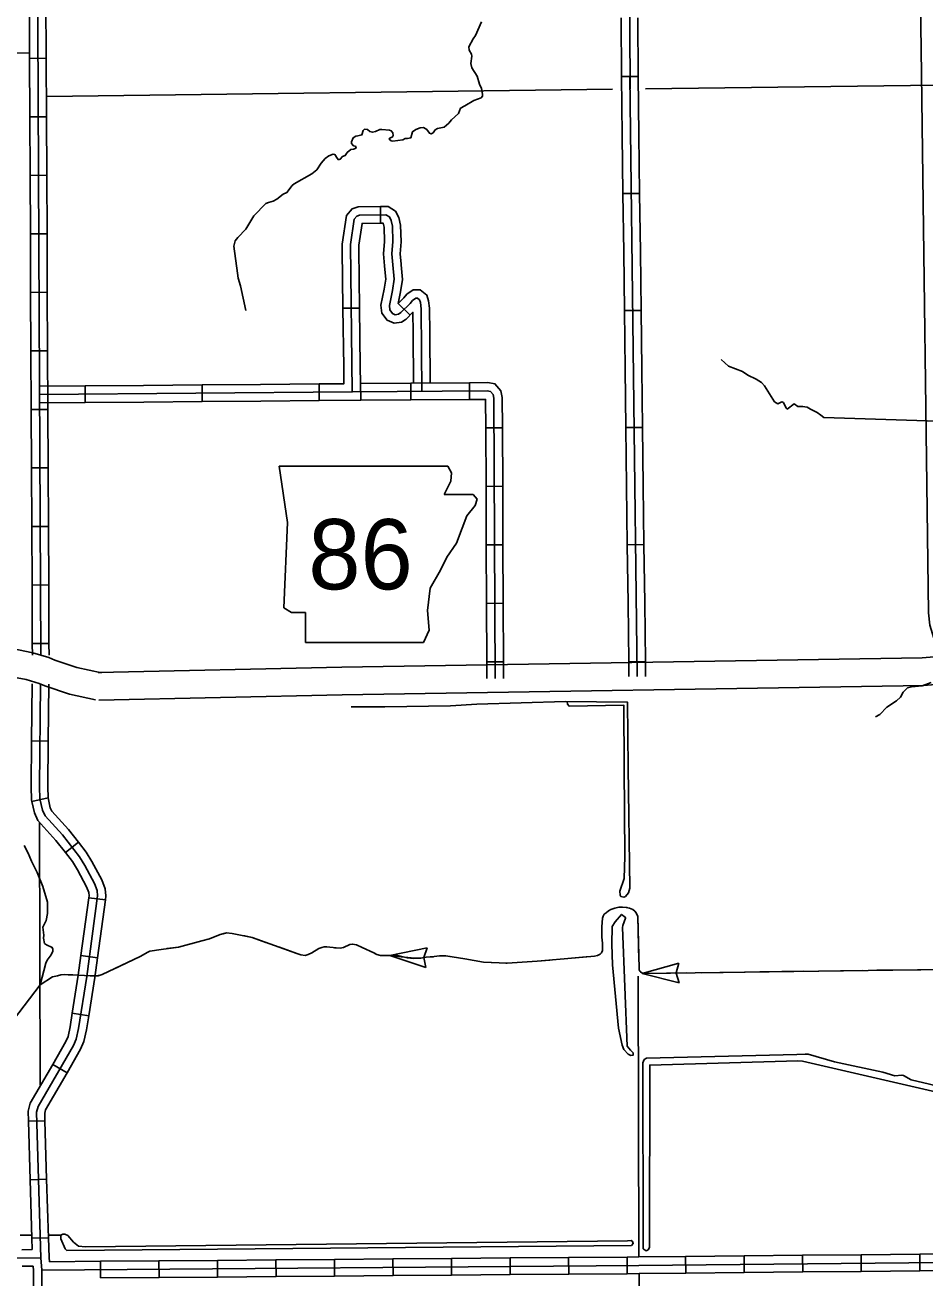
# Model space of a CAD drawing. Extents: x 982240 to 1103002, y 974866 to 1054902.
# Drawn here: x 1049490 to 1057609, y 991826 to 1003130 of the extents above; entities that cross this region are included whole.
import ezdxf

# ---------------------------------------------------------------- set-up
doc = ezdxf.new("R2010")
doc.units = 0
for name, color, linetype in [('10', 7, 'Continuous'), ('21', 7, 'Continuous'), ('32', 7, 'Continuous'), ('35', 7, 'Continuous'), ('4', 7, 'Continuous'), ('43', 7, 'Continuous'), ('45', 7, 'Continuous'), ('5', 7, 'Continuous')]:
    doc.layers.add(name, color=color, linetype=linetype)

msp = doc.modelspace()

# ---------------------------------------------------------------- linework, layer by layer
at = {"layer": '10'}
msp.add_line((1050180, 997286), (1050151, 997289), dxfattribs=at)
for points in [[(1057578, 1002688), (1057529, 1006188)], [(1059251, 997184), (1058283, 997180), (1058154, 997205), (1058053, 997239), (1057965, 997282), (1057854, 997364), (1057744, 997497), (1057688, 997597), (1057654, 997715), (1057641, 997828), (1057578, 1002688)], [(1048814, 997551), (1049247, 997522), (1049432, 997493), (1049560, 997467), (1049704, 997425), (1049760, 997400), (1049958, 997334), (1050180, 997286)], [(1050151, 997289), (1052347, 997337), (1057585, 997420), (1057692, 997430), (1057722, 997438), (1057772, 997463)], [(1050127, 997042), (1049892, 997092), (1049669, 997167), (1049617, 997190), (1049500, 997224), (1049387, 997247), (1049219, 997273), (1048798, 997302)], [(1057964, 997283), (1057942, 997268), (1057811, 997203), (1057737, 997183), (1057598, 997170), (1052351, 997087), (1050156, 997039)]]:
    msp.add_lwpolyline(points, dxfattribs=at)
at = {"layer": '21'}
for p, q in [((1051783, 999150), (1051859, 998643)), ((1053339, 999091), (1053304, 999149)), ((1053331, 999015), (1053339, 999091)), ((1053272, 998896), (1053331, 999015)), ((1053534, 998896), (1053272, 998896)), ((1053568, 998854), (1053534, 998896)), ((1053551, 998795), (1053568, 998854)), ((1053475, 998702), (1053551, 998795)), ((1051859, 998643), (1051825, 997873)), ((1053433, 998592), (1053475, 998702)), ((1053382, 998457), (1053433, 998592)), ((1053297, 998330), (1053382, 998457)), ((1053238, 998211), (1053297, 998330)), ((1053145, 998051), (1053238, 998211)), ((1053120, 997848), (1053145, 998051)), ((1051825, 997873), (1051893, 997831)), ((1051893, 997831), (1052020, 997831)), ((1052020, 997831), (1052020, 997560)), ((1053136, 997670), (1053120, 997848)), ((1053086, 997560), (1053136, 997670)), ((1052020, 997560), (1053086, 997560))]:
    msp.add_line(p, q, dxfattribs=at)
msp.add_lwpolyline([(1051783, 999150), (1053304, 999149)], dxfattribs=at)
at = {"layer": '32'}
for p, q in [((1049681, 1002831), (1049531, 1002830)), ((1049684, 1002303), (1049534, 1002302)), ((1049686, 1001775), (1049536, 1001774)), ((1049689, 1001247), (1049539, 1001246)), ((1049616, 1001142), (1049633, 997446)), ((1049691, 1000719), (1049541, 1000718)), ((1049694, 1000191), (1049544, 1000190)), ((1052972, 999749), (1052971, 999899)), ((1053500, 999752), (1053499, 999902)), ((1049696, 999663), (1049546, 999662)), ((1053647, 999496), (1053797, 999497)), ((1049699, 999135), (1049549, 999134)), ((1053650, 998968), (1053800, 998969)), ((1049701, 998607), (1049551, 998606)), ((1053652, 998440), (1053802, 998441)), ((1049704, 998079), (1049554, 998078)), ((1053654, 997912), (1053804, 997913)), ((1049706, 997551), (1049556, 997550)), ((1053657, 997384), (1053807, 997385)), ((1049699, 996670), (1049549, 996671)), ((1049699, 996158), (1049552, 996126)), ((1049972, 995757), (1049854, 995665)), ((1050215, 995237), (1050066, 995257)), ((1050144, 994714), (1049995, 994734)), ((1050065, 994190), (1049916, 994214)), ((1049870, 993678), (1049740, 993753)), ((1049670, 993244), (1049520, 993240)), ((1049685, 992716), (1049536, 992712)), ((1049701, 992189), (1049551, 992184)), ((1049554, 992082), (1049551, 992184)), ((1049462, 992081), (1049554, 992082)), ((1049710, 991972), (1050170, 991976)), ((1050171, 991826), (1050170, 991976)), ((1050699, 991830), (1050698, 991980)), ((1051227, 991834), (1051226, 991984)), ((1051755, 991839), (1051754, 991989)), ((1052283, 991843), (1052282, 991993)), ((1052811, 991847), (1052810, 991997)), ((1053339, 991851), (1053338, 992001)), ((1053867, 991856), (1053866, 992006)), ((1054395, 991860), (1054394, 992010)), ((1054923, 991864), (1054922, 992014)), ((1055451, 991869), (1055450, 992019)), ((1055979, 991875), (1055978, 992025)), ((1056507, 991880), (1056506, 992030)), ((1057035, 991885), (1057034, 992035)), ((1057563, 991891), (1057562, 992041)), ((1049464, 991931), (1049563, 991932))]:
    msp.add_line(p, q, dxfattribs=at)
for points in [[(1049540, 1018049), (1049562, 1016898), (1049558, 1016757), (1049533, 1016348), (1049537, 1015835), (1049536, 1013831), (1049577, 1008327), (1049592, 1007765), (1049585, 1007779), (1049616, 1001142)], [(1049529, 1003358), (1049531, 1002830)], [(1049679, 1003359), (1049681, 1002831)], [(1049531, 1002830), (1049534, 1002302)], [(1049681, 1002831), (1049684, 1002303)], [(1049534, 1002302), (1049536, 1001774)], [(1049684, 1002303), (1049686, 1001775)], [(1049536, 1001774), (1049539, 1001246)], [(1049686, 1001775), (1049689, 1001247)], [(1049539, 1001246), (1049539, 1001141), (1049541, 1000718)], [(1049689, 1001247), (1049689, 1001142), (1049691, 1000719)], [(1049541, 1000718), (1049544, 1000190)], [(1049691, 1000719), (1049694, 1000191)], [(1049544, 1000190), (1049546, 999662)], [(1049694, 1000191), (1049696, 999663)], [(1052517, 999895), (1052971, 999899)], [(1052971, 999899), (1053499, 999902)], [(1053499, 999902), (1053667, 999904), (1053729, 999894), (1053782, 999831), (1053796, 999771), (1053797, 999497)], [(1052443, 999820), (1053661, 999829), (1053689, 999824), (1053713, 999796), (1053721, 999763), (1053732, 997234)], [(1052972, 999749), (1053500, 999752)], [(1053500, 999752), (1053646, 999753), (1053647, 999496)], [(1049546, 999662), (1049549, 999134)], [(1049696, 999663), (1049699, 999135)], [(1052519, 999745), (1052972, 999749)], [(1053647, 999496), (1053650, 998968)], [(1053797, 999497), (1053800, 998969)], [(1049549, 999134), (1049551, 998606)], [(1049699, 999135), (1049701, 998607)], [(1053650, 998968), (1053652, 998440)], [(1053800, 998969), (1053802, 998441)], [(1049551, 998606), (1049554, 998078)], [(1049701, 998607), (1049704, 998079)], [(1053652, 998440), (1053654, 997912)], [(1053802, 998441), (1053804, 997913)], [(1049554, 998078), (1049556, 997550)], [(1049704, 998079), (1049706, 997551)], [(1053654, 997912), (1053657, 997384)], [(1053804, 997913), (1053807, 997385)], [(1049556, 997550), (1049557, 997445)], [(1049706, 997551), (1049707, 997446)], [(1053657, 997384), (1053657, 997234)], [(1053807, 997385), (1053807, 997234)], [(1049549, 996671), (1049554, 997185)], [(1049633, 992007), (1049594, 993321), (1049608, 993372), (1049926, 993923), (1049951, 993981), (1049972, 994078), (1050047, 994547), (1050145, 995274), (1050140, 995321), (1050116, 995386), (1050030, 995546), (1049981, 995626), (1049827, 995823), (1049671, 995996), (1049648, 996046), (1049625, 996150), (1049622, 996257), (1049631, 997184)], [(1049699, 996670), (1049704, 997183)], [(1049552, 996126), (1049549, 996141), (1049545, 996256), (1049549, 996671)], [(1049699, 996158), (1049699, 996159), (1049695, 996258), (1049699, 996670)], [(1049972, 995757), (1049883, 995871), (1049733, 996037), (1049718, 996069), (1049699, 996158)], [(1049854, 995665), (1049768, 995774), (1049607, 995953), (1049575, 996022), (1049552, 996126)], [(1050215, 995237), (1050220, 995273), (1050212, 995338), (1050183, 995417), (1050094, 995583), (1050042, 995668), (1049972, 995757)], [(1050066, 995257), (1050068, 995274), (1050065, 995303), (1050046, 995355), (1049964, 995508), (1049918, 995582), (1049854, 995665)], [(1049995, 994734), (1050066, 995257)], [(1050144, 994714), (1050215, 995237)], [(1049916, 994214), (1049971, 994558), (1049995, 994734)], [(1050065, 994190), (1050119, 994536), (1050144, 994714)], [(1049740, 993753), (1049858, 993958), (1049878, 994005), (1049897, 994092), (1049916, 994214)], [(1049870, 993678), (1049992, 993890), (1050022, 993959), (1050045, 994064), (1050065, 994190)], [(1049520, 993240), (1049517, 993331), (1049537, 993402), (1049740, 993753)], [(1049670, 993244), (1049668, 993312), (1049676, 993343), (1049870, 993678)], [(1049536, 992712), (1049520, 993240)], [(1049685, 992716), (1049670, 993244)], [(1049551, 992184), (1049536, 992712)], [(1049701, 992189), (1049685, 992716)], [(1049710, 991972), (1049707, 992011), (1049701, 992189)], [(1044184, 991926), (1044962, 991926), (1045714, 991928), (1046055, 991948), (1046598, 991974), (1046943, 991979), (1049633, 992007)], [(1048636, 987556), (1048668, 988356), (1048682, 988479), (1048718, 988660), (1048739, 988714), (1048780, 988797), (1048857, 988890), (1048953, 988965), (1049202, 989123), (1049401, 989241), (1049493, 989319), (1049542, 989378), (1049565, 989413), (1049612, 989529), (1049631, 989654), (1049640, 989959), (1049643, 991895), (1049633, 992007)], [(1049643, 991895), (1055029, 991939), (1057767, 991966)], [(1050170, 991976), (1050698, 991980)], [(1050698, 991980), (1051226, 991984)], [(1051226, 991984), (1051754, 991989)], [(1051754, 991989), (1052282, 991993)], [(1052282, 991993), (1052810, 991997)], [(1052810, 991997), (1053338, 992001)], [(1053338, 992001), (1053866, 992006)], [(1053866, 992006), (1054394, 992010)], [(1054394, 992010), (1054922, 992014)], [(1054922, 992014), (1055028, 992015), (1055450, 992019)], [(1055450, 992019), (1055978, 992025)], [(1055978, 992025), (1056506, 992030)], [(1056506, 992030), (1057034, 992035)], [(1057034, 992035), (1057562, 992041)], [(1057562, 992041), (1057766, 992043), (1058089, 992047)], [(1049566, 991659), (1049566, 991892), (1049563, 991932)], [(1051227, 991834), (1051755, 991839)], [(1051755, 991839), (1052283, 991843)], [(1052283, 991843), (1052811, 991847)], [(1052811, 991847), (1053339, 991851)], [(1053339, 991851), (1053867, 991856)], [(1053867, 991856), (1054395, 991860)], [(1054395, 991860), (1054923, 991864)], [(1054923, 991864), (1055030, 991865), (1055451, 991869)], [(1055451, 991869), (1055979, 991875)], [(1055979, 991875), (1056507, 991880)], [(1056507, 991880), (1057035, 991885)], [(1057035, 991885), (1057563, 991891)], [(1057563, 991891), (1057768, 991893), (1058092, 991897)], [(1050171, 991826), (1050699, 991830)], [(1050699, 991830), (1051227, 991834)]]:
    msp.add_lwpolyline(points, dxfattribs=at)
at = {"layer": '35'}
msp.add_line((1054385, 997003), (1054382, 997027), dxfattribs=at)
for points in [[(1053609, 1003158), (1053555, 1003036), (1053533, 1003006), (1053495, 1002933), (1053498, 1002904), (1053517, 1002868), (1053521, 1002849), (1053513, 1002782), (1053521, 1002743), (1053570, 1002669), (1053590, 1002596), (1053607, 1002557), (1053618, 1002506), (1053618, 1002489), (1053604, 1002475), (1053540, 1002450)], [(1053540, 1002450), (1053458, 1002401), (1053418, 1002380), (1053402, 1002331), (1053339, 1002276), (1053313, 1002245), (1053273, 1002209), (1053210, 1002196), (1053191, 1002185), (1053172, 1002158), (1053154, 1002148), (1053138, 1002156), (1053114, 1002187), (1053086, 1002205), (1053055, 1002203), (1053015, 1002188), (1052986, 1002168), (1052971, 1002114), (1052941, 1002107), (1052920, 1002108), (1052899, 1002096), (1052809, 1002082), (1052792, 1002086), (1052774, 1002102), (1052781, 1002110), (1052807, 1002123), (1052812, 1002133), (1052809, 1002158), (1052794, 1002175), (1052778, 1002181), (1052709, 1002189), (1052691, 1002187), (1052653, 1002169), (1052625, 1002163), (1052601, 1002171), (1052581, 1002188), (1052553, 1002191), (1052541, 1002180), (1052529, 1002139), (1052493, 1002131), (1052475, 1002127), (1052452, 1002113), (1052437, 1002076), (1052437, 1002061), (1052453, 1002041), (1052471, 1002037), (1052477, 1002020), (1052454, 1002009), (1052430, 1002006), (1052398, 1001980), (1052379, 1001953), (1052354, 1001945), (1052334, 1001919), (1052319, 1001915), (1052305, 1001928), (1052286, 1001962), (1052269, 1001964), (1052230, 1001949), (1052197, 1001926), (1052161, 1001885), (1052122, 1001824), (1052078, 1001788), (1051918, 1001699), (1051899, 1001682), (1051853, 1001619), (1051819, 1001604), (1051761, 1001558)], [(1051761, 1001558), (1051729, 1001540), (1051687, 1001530), (1051664, 1001519), (1051554, 1001409), (1051483, 1001289), (1051409, 1001213), (1051387, 1001183), (1051373, 1001135), (1051407, 1000893), (1051414, 1000848), (1051434, 1000777), (1051482, 1000555)], [(1056088, 999935), (1056012, 999971), (1055963, 1000004), (1055838, 1000054), (1055771, 1000112)], [(1057815, 999554), (1056697, 999590), (1056669, 999609), (1056636, 999635), (1056577, 999665), (1056546, 999683), (1056505, 999690), (1056462, 999689), (1056428, 999712), (1056367, 999665), (1056356, 999674), (1056332, 999726), (1056319, 999730), (1056281, 999714), (1056251, 999732), (1056161, 999874), (1056136, 999906), (1056088, 999935)], [(1057664, 997198), (1057585, 997168), (1057487, 997159), (1057451, 997150), (1057413, 997112), (1057389, 997066), (1057352, 997033), (1057264, 996976), (1057203, 996911), (1057162, 996890)], [(1052434, 996980), (1052736, 996979), (1053330, 996987), (1053565, 997004), (1054365, 997027), (1054925, 997022), (1054933, 996433)], [(1054897, 996433), (1054893, 996993), (1054399, 996985), (1054385, 997003)], [(1054933, 996433), (1054947, 995344), (1054934, 995300), (1054907, 995268), (1054892, 995263), (1054866, 995269), (1054859, 995280), (1054858, 995316), (1054897, 995431), (1054902, 995627), (1054897, 996433)], [(1049483, 995728), (1049519, 995660), (1049550, 995586), (1049600, 995483), (1049652, 995358), (1049693, 995217), (1049694, 995114), (1049682, 995051), (1049651, 994992), (1049660, 994920), (1049657, 994891), (1049667, 994844), (1049685, 994830), (1049735, 994807), (1049742, 994792), (1049741, 994773), (1049727, 994741), (1049690, 994693), (1049679, 994667), (1049628, 994471)], [(1054882, 994987), (1054885, 995006), (1054908, 995072), (1054904, 995082), (1054873, 995106), (1054813, 995039), (1054786, 994997), (1054783, 994837), (1054789, 994650), (1054844, 994081), (1054879, 993925), (1054893, 993886), (1054931, 993846), (1054956, 993833), (1054976, 993835), (1054977, 993857), (1054952, 993880), (1054922, 993916), (1054882, 994987)], [(1049628, 994471), (1049385, 994154)], [(1055063, 993748), (1055064, 993767), (1055076, 993796), (1055098, 993808), (1056454, 993841), (1056530, 993846), (1056555, 993844), (1056794, 993776), (1057228, 993683), (1057338, 993649), (1057402, 993657), (1057416, 993654), (1057485, 993614), (1059648, 993103)], [(1059645, 993058), (1056506, 993781), (1056461, 993785), (1055127, 993746), (1055123, 992100), (1055112, 992081), (1055094, 992072), (1055067, 992090), (1055067, 992137)], [(1055067, 992137), (1055063, 993748)], [(1049551, 992213), (1049446, 992213)], [(1049812, 992213), (1049702, 992213)], [(1049812, 992213), (1049831, 992222), (1049849, 992222), (1049876, 992208), (1049928, 992150), (1049974, 992113), (1050035, 992106)], [(1049866, 992074), (1049852, 992088), (1049812, 992179), (1049812, 992213)], [(1054926, 992162), (1054960, 992163), (1054972, 992155), (1054977, 992137), (1054961, 992120), (1049866, 992073)], [(1050035, 992106), (1054926, 992162)]]:
    msp.add_lwpolyline(points, dxfattribs=at)
at = {"layer": '4'}
msp.add_lwpolyline([(1049620, 995938), (1049628, 993567)], dxfattribs=at)
at = {"layer": '43'}
for p, q in [((1052781, 994735), (1053117, 994803)), ((1053117, 994803), (1053088, 994717)), ((1053106, 994626), (1052781, 994735)), ((1053088, 994716), (1053106, 994626)), ((1055058, 994574), (1055389, 994667)), ((1055389, 994667), (1055366, 994578)), ((1055391, 994489), (1055058, 994574)), ((1055366, 994577), (1055391, 994489))]:
    msp.add_line(p, q, dxfattribs=at)
for points in [[(1057988, 994613), (1055091, 994574), (1055066, 994576), (1055056, 994579), (1055043, 994587), (1055038, 994593), (1055032, 994606), (1055030, 994619), (1055018, 995086), (1055004, 995121), (1054993, 995134), (1054975, 995149), (1054945, 995163), (1054914, 995169), (1054881, 995171), (1054846, 995171), (1054812, 995163), (1054774, 995149), (1054755, 995139), (1054733, 995120), (1054716, 995107), (1054707, 995090), (1054699, 995071), (1054695, 994995), (1054695, 994900), (1054700, 994846), (1054699, 994780), (1054691, 994759), (1054679, 994747), (1054654, 994735), (1054627, 994728), (1054594, 994725), (1054111, 994683), (1053841, 994666), (1053627, 994674), (1053457, 994705), (1053286, 994732), (1053231, 994733), (1053180, 994725), (1053110, 994719), (1053062, 994712), (1052999, 994708), (1052937, 994715), (1052878, 994729), (1052840, 994737), (1052800, 994736), (1052771, 994735), (1052737, 994734), (1052698, 994736), (1052664, 994743), (1052638, 994760), (1052531, 994808), (1052482, 994831), (1052444, 994839), (1052422, 994834), (1052362, 994807), (1052332, 994802), (1052297, 994803), (1052214, 994812), (1052189, 994812), (1052169, 994806), (1052140, 994797), (1052077, 994760), (1052046, 994743), (1052017, 994734), (1051978, 994740), (1051943, 994754), (1051540, 994898), (1051449, 994917), (1051360, 994933), (1051308, 994939), (1051251, 994924), (1051154, 994886), (1051084, 994867), (1050874, 994811), (1050717, 994790), (1050617, 994775), (1050593, 994761)], [(1054923, 995167), (1054914, 995169), (1054881, 995171), (1054846, 995171), (1054812, 995163), (1054774, 995149), (1054755, 995139), (1054733, 995120), (1054716, 995107), (1054707, 995090), (1054699, 995071), (1054695, 994995), (1054695, 994940)], [(1055028, 994692), (1055018, 995086), (1055018, 995088)], [(1051472, 994912), (1051449, 994917), (1051360, 994933), (1051308, 994939), (1051278, 994931)], [(1051662, 994854), (1051540, 994898), (1051472, 994912)], [(1050638, 994778), (1050617, 994775), (1050593, 994761), (1050557, 994741), (1050530, 994725), (1050281, 994610)], [(1051154, 994885), (1051084, 994867), (1050874, 994811), (1050769, 994797)], [(1052153, 994801), (1052140, 994797), (1052077, 994760), (1052046, 994743), (1052017, 994734), (1051978, 994740), (1051943, 994754), (1051786, 994810)], [(1052653, 994750), (1052638, 994760), (1052531, 994808), (1052482, 994831), (1052444, 994839), (1052422, 994834), (1052362, 994807), (1052332, 994802), (1052297, 994803), (1052283, 994805)], [(1054700, 994808), (1054699, 994780), (1054691, 994759), (1054679, 994747), (1054654, 994735), (1054627, 994728), (1054594, 994725), (1054553, 994722)], [(1050593, 994761), (1050557, 994741), (1050530, 994725), (1050185, 994565), (1050149, 994553), (1050127, 994553), (1050104, 994552), (1050077, 994553), (1049920, 994560), (1049880, 994562), (1049850, 994563), (1049814, 994560), (1049782, 994553), (1049738, 994542), (1049628, 994471)], [(1053174, 994724), (1053110, 994719), (1053062, 994712), (1053004, 994710), (1052943, 994716), (1052883, 994724), (1052839, 994730), (1052803, 994734), (1052782, 994735)], [(1053697, 994672), (1053627, 994674), (1053457, 994705), (1053305, 994729)], [(1054224, 994693), (1054111, 994683), (1053841, 994666), (1053829, 994667)], [(1054553, 994722), (1054355, 994704)], [(1049969, 994558), (1049920, 994560), (1049880, 994562), (1049850, 994563), (1049814, 994560), (1049782, 994553), (1049767, 994549)], [(1050160, 994557), (1050149, 994553), (1050127, 994553), (1050123, 994553)], [(1055460, 994579), (1055091, 994574), (1055066, 994576), (1055064, 994577)], [(1055988, 994586), (1055592, 994580)], [(1056516, 994593), (1056120, 994587)], [(1056846, 994597), (1056648, 994595)], [(1057044, 994600), (1056846, 994597)], [(1057572, 994607), (1057176, 994602)], [(1049652, 994486), (1049628, 994471)]]:
    msp.add_lwpolyline(points, dxfattribs=at)
at = {"layer": '45'}
for p, q in [((1055022, 1002667), (1054872, 1002666)), ((1054885, 1001610), (1055035, 1001611)), ((1052696, 1001493), (1052698, 1001343)), ((1052358, 1000575), (1052508, 1000577)), ((1052858, 1000618), (1052964, 1000512)), ((1054898, 1000554), (1055048, 1000556)), ((1050032, 999875), (1050033, 999725)), ((1051087, 999884), (1051089, 999734)), ((1052143, 999892), (1052145, 999742)), ((1054911, 999498), (1055061, 999500)), ((1054924, 998442), (1055074, 998444)), ((1054937, 997386), (1055087, 997388))]:
    msp.add_line(p, q, dxfattribs=at)
for points in [[(1054937, 1004778), (1054949, 1002553)], [(1054869, 1003194), (1054872, 1002666)], [(1055019, 1003195), (1055022, 1002667)], [(1054873, 1002666), (1054879, 1002138)], [(1054948, 1002666), (1055014, 997253)], [(1055023, 1002667), (1055029, 1002139)], [(1054879, 1002138), (1054885, 1001610)], [(1055029, 1002139), (1055035, 1001611)], [(1054885, 1001610), (1054892, 1001082)], [(1055035, 1001611), (1055042, 1001084)], [(1052696, 1001493), (1052495, 1001489), (1052441, 1001471), (1052390, 1001412), (1052350, 1001154), (1052351, 1001103)], [(1052883, 1000968), (1052883, 1000972), (1052875, 1001067), (1052883, 1001175), (1052879, 1001326), (1052863, 1001393), (1052834, 1001451), (1052766, 1001494), (1052696, 1001493)], [(1053069, 999824), (1053065, 1000571), (1053057, 1000626), (1053050, 1000650), (1053030, 1000665), (1053015, 1000665), (1052987, 1000646), (1052964, 1000618), (1052882, 1000536), (1052859, 1000521), (1052831, 1000517), (1052804, 1000529), (1052781, 1000560), (1052777, 1000599), (1052804, 1000735), (1052820, 1000837), (1052808, 1000966), (1052800, 1001067), (1052808, 1001176), (1052804, 1001317), (1052792, 1001368), (1052777, 1001399), (1052745, 1001418), (1052507, 1001415), (1052484, 1001407), (1052461, 1001379), (1052426, 1001149), (1052443, 999820), (1049622, 999796)], [(1052698, 1001343), (1052531, 1001340), (1052501, 1001144), (1052501, 1001105)], [(1052733, 1000955), (1052733, 1000959), (1052725, 1001067), (1052733, 1001178), (1052729, 1001307), (1052721, 1001342), (1052721, 1001343), (1052698, 1001343)], [(1052501, 1001105), (1052508, 1000577)], [(1052351, 1001103), (1052358, 1000575)], [(1054892, 1001082), (1054898, 1000554)], [(1055042, 1001084), (1055048, 1000556)], [(1052921, 1000472), (1052886, 1000449), (1052821, 1000440), (1052756, 1000468), (1052708, 1000532), (1052701, 1000602), (1052730, 1000748), (1052744, 1000839), (1052733, 1000955)], [(1052857, 1000617), (1052878, 1000722), (1052895, 1000835), (1052883, 1000968)], [(1053141, 1000353), (1053140, 1000577), (1053131, 1000643), (1053114, 1000694), (1053056, 1000740), (1052991, 1000740), (1052936, 1000701), (1052909, 1000669), (1052857, 1000617)], [(1052358, 1000575), (1052365, 1000047)], [(1052508, 1000577), (1052515, 1000049)], [(1054898, 1000554), (1054905, 1000026)], [(1055048, 1000556), (1055055, 1000028)], [(1052991, 1000352), (1052990, 1000539), (1052930, 1000478), (1052921, 1000472)], [(1052994, 999899), (1052991, 1000352)], [(1053144, 999900), (1053141, 1000353)], [(1052365, 1000047), (1052367, 999894), (1052143, 999892)], [(1052515, 1000049), (1052519, 999745), (1052145, 999742)], [(1054905, 1000026), (1054911, 999498)], [(1055055, 1000028), (1055061, 999500)], [(1050032, 999875), (1049621, 999871)], [(1050560, 999879), (1050032, 999875)], [(1051087, 999884), (1050560, 999879)], [(1051615, 999888), (1051087, 999884)], [(1052143, 999892), (1051615, 999888)], [(1050033, 999725), (1049623, 999721)], [(1050561, 999729), (1050033, 999725)], [(1051089, 999734), (1050561, 999729)], [(1051617, 999738), (1051089, 999734)], [(1052145, 999742), (1051617, 999738)], [(1054911, 999498), (1054918, 998970)], [(1055061, 999500), (1055068, 998972)], [(1054918, 998970), (1054924, 998442)], [(1055068, 998972), (1055074, 998444)], [(1054924, 998442), (1054931, 997914)], [(1055074, 998444), (1055081, 997916)], [(1054931, 997914), (1054937, 997386)], [(1055081, 997916), (1055087, 997388)], [(1054937, 997386), (1054939, 997252)], [(1055087, 997388), (1055089, 997254)]]:
    msp.add_lwpolyline(points, dxfattribs=at)
at = {"layer": '5'}
for points in [[(1047537, 1002843), (1049532, 1002879)], [(1054948, 1002667), (1054949, 1002553)], [(1055089, 1002555), (1057717, 1002588)], [(1049687, 1002487), (1054789, 1002551)], [(1055022, 994548), (1055029, 992015)], [(1055030, 991865), (1055051, 989288)]]:
    msp.add_lwpolyline(points, dxfattribs=at)

# ---------------------------------------------------------------- texts
at = {"layer": '21'}
msp.add_text('86', height=633.6, dxfattribs=at).set_placement((1052046, 998039))

doc.saveas('drawing.dxf')
